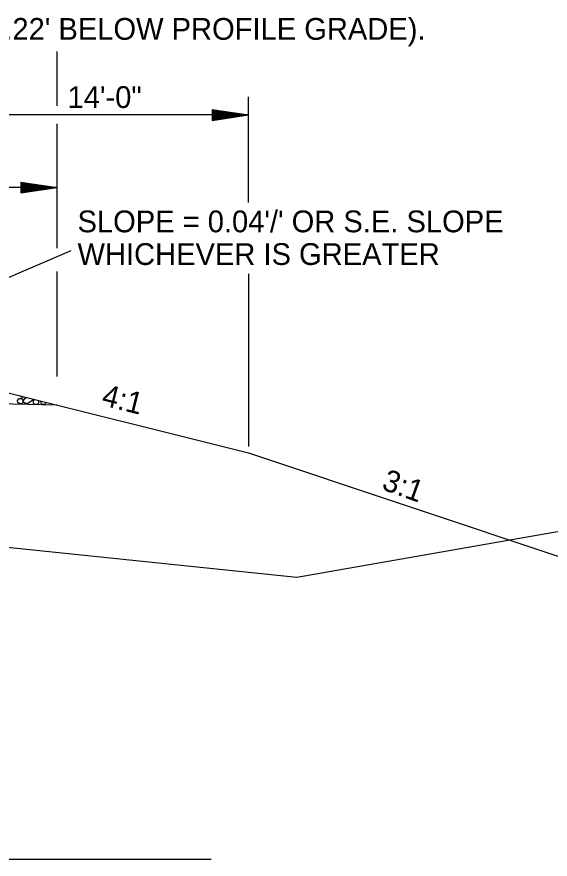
# Model space of a CAD drawing. Extents: x 2478 to 3210, y 439 to 841.
# Drawn here: x 2664.77 to 2694.17, y 562.28 to 608.68 of the extents above; entities that cross this region are included whole.
import ezdxf

# ---------------------------------------------------------------- set-up
doc = ezdxf.new("R2010")
doc.units = 0
for name, color, linetype in [('R_Annotation', 7, 'Continuous'), ('R_Dimension', 7, 'Continuous'), ('R_Exist Surface', 7, 'Continuous')]:
    doc.layers.add(name, color=color, linetype=linetype)

msp = doc.modelspace()

# ---------------------------------------------------------------- linework, layer by layer
at = {"layer": 'R_Annotation'}
for p, q in [((2657.543, 589.654), (2677.543, 584.654)), ((2666.995, 587.291), (2605.543, 588.52)), ((2677.543, 584.654), (2695.043, 578.821)), ((2580.788, 562.276), (2675.476, 562.276))]:
    msp.add_line(p, q, dxfattribs=at)
at = {"layer": 'R_Dimension'}
for p, q in [((2666.995, 603.781), (2666.995, 606.78)), ((2677.543, 598.45), (2677.543, 604.281)), ((2675.543, 603.581), (2677.543, 603.281)), ((2675.543, 603.581), (2675.543, 602.981)), ((2675.543, 603.531), (2677.209, 603.281)), ((2675.543, 603.48), (2676.865, 603.281)), ((2675.543, 603.43), (2676.532, 603.281)), ((2675.543, 603.378), (2676.193, 603.281)), ((2675.543, 603.328), (2675.859, 603.281)), ((2677.543, 603.281), (2649.543, 603.281)), ((2675.543, 602.981), (2677.543, 603.281)), ((2675.543, 603.183), (2676.193, 603.281)), ((2675.543, 603.082), (2676.865, 603.281)), ((2675.543, 603.031), (2677.209, 603.281)), ((2675.543, 603.132), (2676.532, 603.281)), ((2675.543, 603.234), (2675.859, 603.281)), ((2666.995, 595.936), (2666.995, 602.781)), ((2666.995, 599.281), (2586.003, 599.281)), ((2664.995, 599.581), (2666.995, 599.281)), ((2664.995, 599.581), (2664.995, 598.981)), ((2664.995, 599.531), (2666.661, 599.281)), ((2664.995, 599.48), (2666.317, 599.281)), ((2664.995, 599.43), (2665.984, 599.281)), ((2664.995, 599.378), (2665.645, 599.281)), ((2664.995, 599.328), (2665.311, 599.281)), ((2664.995, 598.981), (2666.995, 599.281)), ((2664.995, 599.183), (2665.645, 599.281)), ((2664.995, 599.082), (2666.317, 599.281)), ((2664.995, 599.031), (2666.661, 599.281)), ((2664.995, 599.132), (2665.984, 599.281)), ((2664.995, 599.234), (2665.311, 599.281)), ((2653.822, 589.875), (2667.759, 595.805)), ((2666.995, 588.866), (2666.995, 594.662)), ((2677.543, 594.524), (2677.543, 585.014)), ((2665.273, 587.714), (2665.284, 587.719)), ((2665.668, 587.504), (2665.744, 587.604)), ((2666.088, 587.504), (2666.096, 587.516)), ((2666.938, 587.292), (2666.958, 587.301))]:
    msp.add_line(p, q, dxfattribs=at)
for points in [[(2664.808, 587.539), (2664.893, 587.654), (2665.023, 587.659), (2665.103, 587.569), (2665.093, 587.439), (2665.018, 587.369), (2664.893, 587.379), (2664.823, 587.439), (2664.808, 587.539)], [(2665.153, 587.752), (2665.138, 587.734), (2665.023, 587.734), (2664.938, 587.806)], [(2665.634, 587.631), (2665.633, 587.589), (2665.528, 587.464), (2665.378, 587.384), (2665.228, 587.379), (2665.148, 587.439), (2665.143, 587.554), (2665.208, 587.659), (2665.278, 587.72)], [(2665.942, 587.555), (2665.968, 587.524), (2665.958, 587.399), (2665.883, 587.329), (2665.753, 587.334), (2665.693, 587.399), (2665.668, 587.489)], [(2666.38, 587.445), (2666.373, 587.399), (2666.298, 587.334), (2666.173, 587.344), (2666.113, 587.404), (2666.088, 587.504)]]:
    msp.add_lwpolyline(points, dxfattribs=at)
at = {"layer": 'R_Exist Surface'}
msp.add_lwpolyline([(2559.048, 580.013), (2580.798, 583.038), (2610.269, 580.01), (2642.749, 581.692), (2680.214, 577.819), (2705.082, 582.167)], dxfattribs=at)

# ---------------------------------------------------------------- texts
at = {"layer": 'R_Annotation'}
for s, p in [("(0.22' BELOW PROFILE GRADE).", (2662.652, 607.42)), ('14\'-0"', (2667.565, 603.663)), ("SLOPE = 0.04'/' OR S.E. SLOPE", (2668.114, 596.814)), ('WHICHEVER IS GREATER', (2668.114, 595.014))]:
    msp.add_text(s, height=1.2, dxfattribs=at).set_placement(p)
for s, rotation, p in [('4:1', 345.964, (2669.384, 587.299)), ('3:1', 340.1739, (2684.831, 582.669))]:
    msp.add_text(s, height=1.2, rotation=rotation, dxfattribs=at).set_placement(p)

doc.saveas('drawing.dxf')
